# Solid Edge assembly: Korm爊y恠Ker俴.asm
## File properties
Author: morva
Template: iso metric assembly.asm
Last saved by: morva
Revision: 48
Application: Solid Edge
Username: morva
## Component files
001176_R.asm
KORMNY~2.PAR
Tok.par
Pin.par
KOA71B~1.PAR
Villa.par
kormany2.par
SKF_51104.asm
Seat Clamp tube 27.2mm X 20mm angle.asm
ny1.par
hex_socket_countersunk_flat_head_M8x20.par
001176_L.asm
mudcatcher.par
kDummy.par
throttledummy.par
kijelzodummy.par
markolatdummy.par
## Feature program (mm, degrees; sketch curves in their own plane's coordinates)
fearecompute load "unnamed FEARecomputeLoad 1"
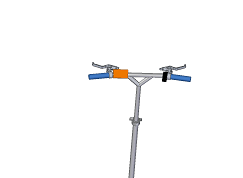
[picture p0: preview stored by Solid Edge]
